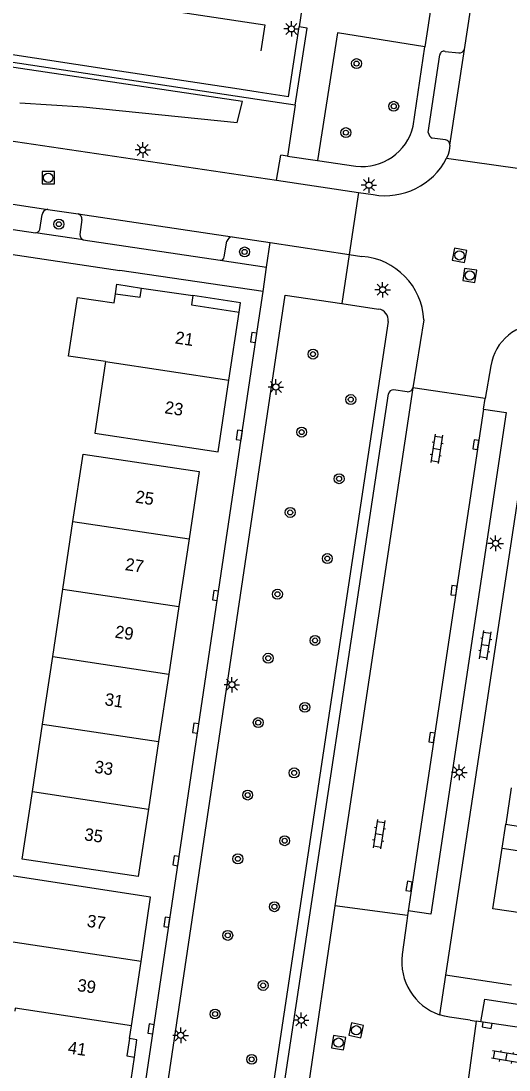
# Model space of a CAD drawing. Extents: x 124000 to 128010, y 398999 to 403000.
# Drawn here: x 126538.7 to 126578, y 399996.7 to 400081.2 of the extents above; entities that cross this region are included whole.
import ezdxf

# ---------------------------------------------------------------- set-up
doc = ezdxf.new("R2010")
doc.units = 0
for name, color, linetype in [('gg-afsc-hekwerk', 7, 'Continuous'), ('gg-anno-huisnummerreeks BGT', 7, 'Continuous'), ('gg-bbg-gedigitaliseerde bebouwing', 7, 'Continuous'), ('gg-bbg-hoofdgebouw', 7, 'Continuous'), ('gg-bbg-onder overbouw', 7, 'Continuous'), ('gg-bbg-pand overbouw', 7, 'Continuous'), ('gg-bbg-tussenscheiding', 7, 'Continuous'), ('gg-knt-verharding', 7, 'Continuous'), ('gg-knt-verharding nz', 7, 'Continuous'), ('gg-kntw-greppel-droge sloot', 7, 'Continuous'), ('gt-grn-groengrens', 7, 'Continuous'), ('gt-grn-weggrens', 7, 'Continuous'), ('gt-symb-boom', 7, 'Continuous'), ('gt-symb-klinker verharding', 7, 'Continuous'), ('gt-symb-kolk', 7, 'Continuous'), ('gt-symb-lichtmast', 7, 'Continuous'), ('gt-symb-rioolschacht', 7, 'Continuous')]:
    doc.layers.add(name, color=color, linetype=linetype)

# ---------------------------------------------------------------- blocks, each defined once
blk = doc.blocks.new('gt0-BOOM')
at = {"layer": 'gt-symb-boom'}
for radius in [0.4, 0.2]:
    blk.add_circle((0, 0), radius, dxfattribs=at)
blk = doc.blocks.new('gt0-RS')
at = {"layer": 'gt-symb-rioolschacht'}
blk.add_lwpolyline([(-0.5, -0.5), (0.5, -0.5), (0.5, 0.5), (-0.5, 0.5)], close=True, dxfattribs=at)
blk.add_circle((0, 0), 0.375, dxfattribs=at)
blk = doc.blocks.new('gt0-LMAST')
at = {"layer": 'gt-symb-lichtmast'}
for p, q in [((-0.182, 0.173), (-0.447, 0.438)), ((-0.005, 0.246), (-0.005, 0.621)), ((0.172, 0.173), (0.437, 0.438)), ((-0.255, -0.004), (-0.63, -0.004)), ((-0.182, -0.181), (-0.447, -0.446)), ((-0.005, -0.254), (-0.005, -0.629)), ((0.437, -0.446), (0.172, -0.181)), ((0.245, -0.004), (0.62, -0.004))]:
    blk.add_line(p, q, dxfattribs=at)
blk.add_circle((-0.005, -0.004), 0.25, dxfattribs=at)
blk = doc.blocks.new('gt0-KOLK')
at = {"layer": 'gt-symb-kolk'}
blk.add_lwpolyline([(0, 0), (0.375, 0), (0.375, 0.4), (-0.375, 0.4), (-0.375, 0), (0, 0)], dxfattribs=at)
blk = doc.blocks.new('gt0-KL1')
at = {"layer": 'gt-symb-klinker verharding'}
for p, q in [((-1.15, 0.3), (1.15, 0.3)), ((-1, -0.3), (-1, 0.3)), ((-0.5, 0.3), (-0.5, 0.45)), ((0, -0.3), (0, 0.3)), ((0.5, 0.3), (0.5, 0.45)), ((1, -0.3), (1, 0.3)), ((-1.15, -0.3), (1.15, -0.3)), ((-0.5, -0.45), (-0.5, -0.3)), ((0.5, -0.45), (0.5, -0.3))]:
    blk.add_line(p, q, dxfattribs=at)

msp = doc.modelspace()

# ---------------------------------------------------------------- linework, layer by layer
at = {"layer": 'gg-afsc-hekwerk'}
for p, q in [((126561.649, 400084.306), (126561.097, 400080.675)), ((126546.085, 400077.203), (126519.357, 400081.26)), ((126560.242, 400075.054), (126561.097, 400080.675)), ((126555.921, 400075.71), (126546.085, 400077.203)), ((126557.795, 400075.425), (126555.921, 400075.71)), ((126560.242, 400075.054), (126557.795, 400075.425)), ((126535.495, 400062.741), (126546.659, 400061.069))]:
    msp.add_line(p, q, dxfattribs=at)
msp.add_lwpolyline([(126548.487, 400082.312), (126558.34, 400080.838), (126558.01, 400078.764)], dxfattribs=at)
at = {"layer": 'gg-bbg-gedigitaliseerde bebouwing'}
msp.add_lwpolyline([(126545.479, 400053.72), (126542.521, 400054.159), (126543.222, 400058.885), (126546.18, 400058.446), (126546.289, 400059.178)], dxfattribs=at)
at = {"layer": 'gg-bbg-hoofdgebouw'}
for p, q in [((126548.398, 400059.65), (126552.534, 400059.037)), ((126555.437, 400052.241), (126556.257, 400057.709)), ((126542.051, 400035.406), (126542.868, 400040.842)), ((126552.231, 400039.437), (126551.409, 400033.999)), ((126541.233, 400029.971), (126542.051, 400035.406)), ((126551.409, 400033.999), (126550.587, 400028.561)), ((126540.416, 400024.536), (126541.233, 400029.971)), ((126550.587, 400028.561), (126549.765, 400023.122)), ((126539.599, 400019.1), (126540.416, 400024.536)), ((126549.765, 400023.122), (126548.943, 400017.684)), ((126577.453, 400014.541), (126577.749, 400016.475)), ((126547.574, 400000.236), (126548.352, 400005.414)), ((126547.419, 399999.202), (126547.574, 400000.236)), ((126547.425, 399994.963), (126547.825, 399997.697))]:
    msp.add_line(p, q, dxfattribs=at)
for points in [[(126545.479, 400053.72), (126544.625, 400047.967), (126554.572, 400046.467), (126555.437, 400052.241)], [(126542.868, 400040.842), (126543.685, 400046.277), (126553.053, 400044.875), (126552.231, 400039.437)], [(126548.943, 400017.684), (126548.121, 400012.246), (126538.782, 400013.665), (126539.599, 400019.1)], [(126579.092, 400009.291), (126576.702, 400009.644), (126577.453, 400014.541)], [(126548.352, 400005.414), (126549.13, 400010.592), (126537.416, 400012.379), (126536.631, 400007.178)]]:
    msp.add_lwpolyline(points, dxfattribs=at)
at = {"layer": 'gg-bbg-onder overbouw'}
for points in [[(126546.289, 400059.178), (126548.297, 400058.905), (126548.398, 400059.65)], [(126552.534, 400059.037), (126552.426, 400058.306), (126556.257, 400057.709)], [(126577.749, 400016.475), (126578.915, 400016.296), (126579.36, 400019.222)], [(126547.419, 399999.202), (126547.209, 399997.801), (126547.825, 399997.697)]]:
    msp.add_lwpolyline(points, dxfattribs=at)
at = {"layer": 'gg-bbg-pand overbouw'}
msp.add_line((126578.191, 400019.399), (126577.749, 400016.475), dxfattribs=at)
for points in [[(126546.289, 400059.178), (126546.403, 400059.946), (126548.398, 400059.65)], [(126556.257, 400057.709), (126556.37, 400058.462), (126552.534, 400059.037)], [(126547.825, 399997.697), (126548.029, 399999.11), (126547.419, 399999.202)]]:
    msp.add_lwpolyline(points, dxfattribs=at)
at = {"layer": 'gg-bbg-tussenscheiding'}
for p, q in [((126545.479, 400053.72), (126555.437, 400052.241)), ((126542.868, 400040.842), (126552.231, 400039.437)), ((126542.051, 400035.406), (126551.409, 400033.999)), ((126541.233, 400029.971), (126550.587, 400028.561)), ((126540.416, 400024.536), (126549.765, 400023.122)), ((126539.599, 400019.1), (126548.943, 400017.684)), ((126577.453, 400014.541), (126586.985, 400013.094)), ((126548.352, 400005.414), (126536.631, 400007.178))]:
    msp.add_line(p, q, dxfattribs=at)
msp.add_lwpolyline([(126547.574, 400000.236), (126538.213, 400001.644), (126538.177, 400001.403)], dxfattribs=at)
at = {"layer": 'gg-knt-verharding'}
for p, q in [((126574.424, 400078.864), (126574.902, 400082.036)), ((126472.908, 400081.167), (126559.26, 400068.335)), ((126570.293, 400072.68), (126571.225, 400079.077)), ((126571.506, 400072.162), (126572.431, 400078.423)), ((126572.856, 400078.705), (126573.954, 400078.591)), ((126560.785, 400074.365), (126560.152, 400070.263)), ((126572.904, 400071.573), (126571.82, 400071.727)), ((126559.26, 400068.335), (126559.612, 400070.341)), ((126560.152, 400070.263), (126559.612, 400070.341)), ((126562.574, 400069.915), (126565.665, 400069.47)), ((126572.978, 400070.109), (126578.892, 400069.278)), ((126559.26, 400068.335), (126565.875, 400067.351)), ((126565.875, 400067.351), (126565.124, 400062.357)), ((126565.875, 400067.351), (126567.058, 400067.172)), ((126528.882, 400065.733), (126539.839, 400064.105)), ((126540.205, 400064.365), (126540.386, 400065.561)), ((126540.836, 400065.986), (126543.3, 400065.611)), ((126543.581, 400065.166), (126543.42, 400063.958)), ((126543.689, 400063.521), (126539.839, 400064.105)), ((126543.689, 400063.521), (126554.745, 400061.882)), ((126555.05, 400062.154), (126555.279, 400063.421)), ((126555.712, 400063.767), (126558.767, 400063.309)), ((126558.47, 400061.325), (126558.767, 400063.309)), ((126558.767, 400063.309), (126565.124, 400062.357)), ((126565.124, 400062.357), (126566.159, 400062.194)), ((126554.745, 400061.882), (126558.47, 400061.325)), ((126558.199, 400059.361), (126546.659, 400061.069)), ((126564.536, 400058.396), (126567.501, 400057.956)), ((126568.277, 400056.948), (126558.558, 399992.577)), ((126571.143, 400057.078), (126570.259, 400051.611)), ((126569.804, 400051.301), (126568.713, 400051.441)), ((126576.092, 400050.75), (126570.259, 400051.611)), ((126559.514, 399993.007), (126568.296, 400051.129)), ((126575.966, 400049.892), (126576.092, 400050.75)), ((126579.76, 400049.716), (126572.89, 400004.317)), ((126569.824, 400009.125), (126563.964, 400009.884)), ((126569.872, 400009.49), (126569.824, 400009.125)), ((126578.208, 400003.509), (126572.89, 400004.317)), ((126575.352, 400000.616), (126574.684, 399995.664)), ((126575.731, 400000.561), (126575.352, 400000.616))]:
    msp.add_line(p, q, dxfattribs=at)
for points in [[(126560.785, 400074.365), (126561.744, 400080.573), (126561.097, 400080.675)], [(126571.225, 400079.077), (126564.176, 400080.19), (126562.574, 400069.915)], [(126573.238, 400071.157), (126573.194, 400070.701), (126573.104, 400070.399), (126572.978, 400070.109)], [(126547.67, 399988.692), (126548.039, 399991.094), (126557.636, 400055.631), (126558.199, 400059.361)], [(126554.196, 399987.68), (126553.742, 399987.742), (126549.437, 399988.393), (126559.973, 400059.074), (126564.536, 400058.396)], [(126575.966, 400049.892), (126577.781, 400049.636), (126571.718, 400009.223), (126569.872, 400009.49)], [(126575.731, 400000.561), (126576.072, 400002.367), (126594.728, 399999.544), (126594.485, 399997.72)]]:
    msp.add_lwpolyline(points, dxfattribs=at)
for centre, radius, start, end in [((126572.76, 400078.388), 0.331, 73.13328, 173.99761), ((126574.002, 400079.05), 0.461, 264.03065, 336.26976), ((126566.176, 400073.675), 4.236, 263.07168, 346.41899), ((126572.121, 400072.275), 0.625, 190.40021, 241.24624), ((126572.871, 400071.204), 0.37, 352.64243, 84.87846), ((126568.04, 400072.627), 5.543, 259.79391, 332.97948), ((126540.862, 400065.508), 0.479, 93.08458, 173.64226), ((126543.186, 400065.228), 0.4, 351.08992, 73.45168), ((126539.867, 400064.453), 0.349, 265.32712, 345.45152), ((126543.893, 400063.948), 0.473, 178.76605, 244.46359), ((126555.745, 400063.282), 0.486, 93.88982, 163.36522), ((126565.763, 400056.823), 5.386, 2.71699, 85.78547), ((126554.748, 400062.186), 0.304, 269.46303, 353.99033), ((126567.343, 400057.032), 0.938, 354.88792, 80.2932), ((126568.683, 400051.047), 0.395, 85.5938, 168.01398), ((126569.865, 400051.7), 0.404, 261.2652, 347.26947)]:
    msp.add_arc(centre, radius, start, end, dxfattribs=at)
at = {"layer": 'gg-knt-verharding nz'}
for p, q in [((126573.238, 400071.157), (126574.424, 400078.864)), ((126528.444, 400067.831), (126540.836, 400065.986)), ((126543.3, 400065.611), (126555.712, 400063.767)), ((126576.537, 400053.372), (126576.092, 400050.75)), ((126570.259, 400051.611), (126563.964, 400009.884)), ((126575.966, 400049.892), (126569.872, 400009.49)), ((126563.964, 400009.884), (126561.433, 399992.717)), ((126569.824, 400009.125), (126569.768, 400008.697)), ((126569.768, 400008.697), (126569.411, 400005.962)), ((126574.874, 400000.686), (126575.352, 400000.616)), ((126594.485, 399997.72), (126575.731, 400000.561))]:
    msp.add_line(p, q, dxfattribs=at)
msp.add_lwpolyline([(126574.874, 400000.686), (126573.225, 400000.925), (126572.807, 400001.006), (126572.4, 400001.126)], dxfattribs=at)
for centre, radius, start, end in [((126580.493, 400052.743), 4.006, 87.45911, 170.96405), ((126573.87, 400005.376), 4.498, 172.51897, 250.91919)]:
    msp.add_arc(centre, radius, start, end, dxfattribs=at)
at = {"layer": 'gg-kntw-greppel-droge sloot'}
msp.add_lwpolyline([(126538.574, 400074.557), (126543.685, 400074.243), (126556.112, 400072.987), (126556.542, 400074.659), (126536.631, 400077.615), (126532.972, 400077.635), (126529.622, 400077.297), (126526.318, 400077.178), (126494.729, 400081.991)], dxfattribs=at)
at = {"layer": 'gt-grn-groengrens'}
for p, q in [((126557.706, 400074.832), (126474.051, 400087.531)), ((126560.785, 400074.365), (126557.706, 400074.832))]:
    msp.add_line(p, q, dxfattribs=at)
at = {"layer": 'gt-grn-weggrens'}
for p, q in [((126571.782, 400082.755), (126571.225, 400079.077)), ((126560.152, 400070.263), (126562.574, 400069.915)), ((126565.124, 400062.357), (126564.536, 400058.396)), ((126558.199, 400059.361), (126558.47, 400061.325)), ((126572.89, 400004.317), (126572.4, 400001.126))]:
    msp.add_line(p, q, dxfattribs=at)

# ---------------------------------------------------------------- block references
at = {"layer": 'gt-symb-boom'}
for p in [(126565.723, 400077.724), (126568.72, 400074.286), (126564.862, 400072.164), (126541.732, 400064.791), (126556.702, 400062.557), (126562.216, 400054.326), (126565.258, 400050.669), (126561.3, 400048.046), (126564.317, 400044.29), (126560.376, 400041.573), (126563.367, 400037.862), (126559.348, 400034.99), (126562.378, 400031.268), (126558.603, 400029.837), (126561.561, 400025.88), (126557.802, 400024.651), (126560.696, 400020.6), (126556.949, 400018.815), (126559.933, 400015.136), (126556.159, 400013.679), (126559.104, 400009.822), (126555.344, 400007.515), (126558.195, 400003.481), (126554.321, 400001.181), (126557.272, 399997.529)]:
    msp.add_blockref('gt0-BOOM', p, dxfattribs=at)
at = {"layer": 'gt-symb-klinker verharding'}
for p, rotation in [((126572.177, 400046.695), -98.56758990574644), ((126576.098, 400030.881), 81.37577126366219), ((126567.54, 400015.665), -98.56758990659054), ((126577.774, 399997.722), 170.62242087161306)]:
    msp.add_blockref('gt0-KL1', p, dxfattribs=dict(at, rotation=rotation))
at = {"layer": 'gt-symb-kolk'}
for p, rotation in [((126557.636, 400055.631), 81.40538754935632), ((126556.469, 400047.772), 81.55263081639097), ((126575.139, 400047.064), -98.2758928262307), ((126554.552, 400034.861), 81.55263081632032), ((126573.766, 400035.273), 82.87498365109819), ((126552.957, 400024.168), 81.51951448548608), ((126571.989, 400023.418), 81.19719554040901), ((126551.374, 400013.495), 81.56061323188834), ((126570.16, 400011.439), 81.31914941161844), ((126550.632, 400008.549), 81.4624506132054), ((126576.272, 400000.475), 171.3757712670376), ((126549.359, 399999.95), 81.58574340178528)]:
    msp.add_blockref('gt0-KOLK', p, dxfattribs=dict(at, rotation=rotation))
at = {"layer": 'gt-symb-lichtmast'}
for p in [(126560.484, 400080.523), (126548.5, 400070.773), (126566.724, 400067.938), (126567.832, 400059.511), (126559.225, 400051.679), (126576.939, 400039.091), (126555.682, 400027.701), (126574.011, 400020.649), (126561.271, 400000.683), (126551.56, 399999.467)]:
    msp.add_blockref('gt0-LMAST', p, dxfattribs=at)
at = {"layer": 'gt-symb-rioolschacht'}
msp.add_blockref('gt0-RS', (126540.878, 400068.527), dxfattribs=at)
for p, rotation in [((126574.018, 400062.279), -10.950434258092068), ((126574.848, 400060.659), -8.9726266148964), ((126565.698, 399999.868), 77.52092819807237), ((126564.276, 399998.875), 80.20785375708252)]:
    msp.add_blockref('gt0-RS', p, dxfattribs=dict(at, rotation=rotation))

# ---------------------------------------------------------------- texts
at = {"layer": 'gg-anno-huisnummerreeks BGT'}
for s, rotation, p in [('21', 351.5, (126551.049, 400055.189)), ('23', 351.5, (126550.207, 400049.568)), ('25', 351.4, (126547.844, 400042.376)), ('27', 351.4, (126547.022, 400036.938)), ('29', 351.4, (126546.2, 400031.5)), ('31', 351.4, (126545.378, 400026.061)), ('33', 351.4, (126544.556, 400020.623)), ('35', 351.4, (126543.734, 400015.185)), ('37', 351.5, (126543.943, 400008.218)), ('39', 351.5, (126543.166, 400003.04)), ('41', 351.5, (126542.411, 399998.017))]:
    msp.add_text(s, height=1, rotation=rotation, dxfattribs=at).set_placement(p)

doc.saveas('drawing.dxf')
